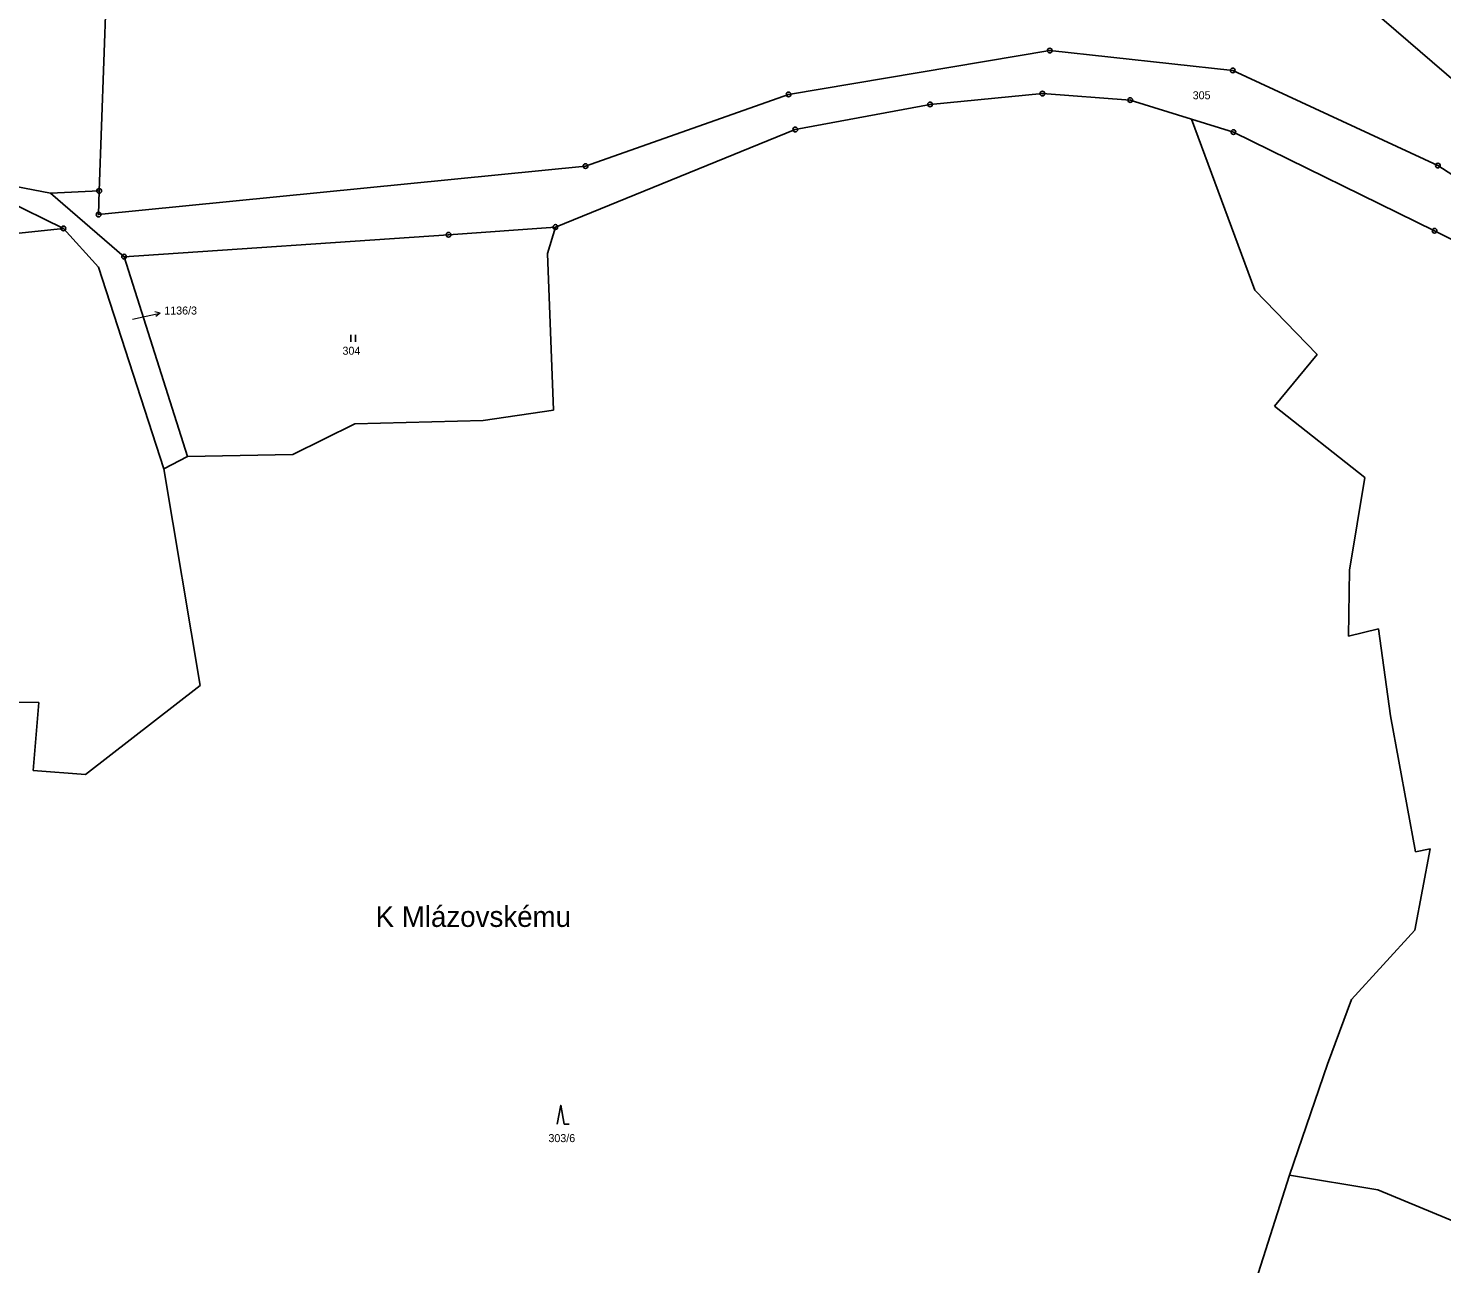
# Model space of a CAD drawing. Extents: x -765428 to -762163, y -1107632 to -1104975.
# Drawn here: x -763569.2 to -763268.9, y -1106861.1 to -1106598.6 of the extents above; entities that cross this region are included whole.
import ezdxf

# ---------------------------------------------------------------- set-up
doc = ezdxf.new("R2010")
doc.units = 0
doc.header["$LTSCALE"] = 0.68
for name, color, linetype, lineweight in [('1', 7, 'Continuous', 25), ('3', 7, 'Continuous', 25), ('7', 7, 'Continuous', 13), ('8', 7, 'Continuous', 25)]:
    doc.layers.add(name, color=color, linetype=linetype, lineweight=lineweight)
doc.layers.add('2', color=7, linetype='Continuous')

msp = doc.modelspace()

# ---------------------------------------------------------------- linework, layer by layer
at = {"layer": '1'}
for p, q in [((-763552.49, -1106587.5), (-763554.12, -1106633.15)), ((-763284.2, -1106594.34), (-763265.37, -1106610.51)), ((-763352.19, -1106603.34), (-763407.67, -1106612.64)), ((-763313.3, -1106607.56), (-763352.19, -1106603.34)), ((-763269.72, -1106627.78), (-763313.3, -1106607.56)), ((-763407.67, -1106612.64), (-763450.79, -1106627.87)), ((-763377.61, -1106614.76), (-763406.25, -1106620.1)), ((-763353.75, -1106612.47), (-763377.61, -1106614.76)), ((-763335.07, -1106613.84), (-763353.75, -1106612.47)), ((-763322.09, -1106617.87), (-763335.07, -1106613.84)), ((-763308.58, -1106654.21), (-763322.09, -1106617.87)), ((-763313.15, -1106620.65), (-763322.09, -1106617.87)), ((-763406.25, -1106620.1), (-763457.18, -1106640.82)), ((-763270.44, -1106641.61), (-763313.15, -1106620.65)), ((-763564.46, -1106633.61), (-763588.74, -1106629.05)), ((-763554.26, -1106638.18), (-763450.79, -1106627.87)), ((-763247.51, -1106642.16), (-763269.72, -1106627.78)), ((-763561.73, -1106641.13), (-763574.06, -1106635.01)), ((-763554.12, -1106633.15), (-763564.46, -1106633.61)), ((-763548.81, -1106647.12), (-763564.46, -1106633.61)), ((-763554.12, -1106633.15), (-763554.26, -1106638.18)), ((-763582.01, -1106643.26), (-763561.73, -1106641.13)), ((-763561.73, -1106641.13), (-763554.28, -1106649.38)), ((-763457.18, -1106640.82), (-763479.9, -1106642.48)), ((-763458.89, -1106646.44), (-763457.18, -1106640.82)), ((-763243.17, -1106655.54), (-763270.44, -1106641.61)), ((-763479.9, -1106642.48), (-763548.81, -1106647.12)), ((-763548.81, -1106647.12), (-763535.32, -1106689.59)), ((-763457.61, -1106679.72), (-763458.89, -1106646.44)), ((-763554.28, -1106649.38), (-763540.36, -1106692.2)), ((-763308.58, -1106654.21), (-763295.34, -1106667.93)), ((-763295.34, -1106667.93), (-763304.45, -1106678.85)), ((-763472.56, -1106681.93), (-763457.61, -1106679.72)), ((-763304.45, -1106678.85), (-763285.25, -1106694.03)), ((-763513, -1106689.13), (-763499.8, -1106682.66)), ((-763499.8, -1106682.66), (-763472.56, -1106681.93)), ((-763535.32, -1106689.59), (-763513, -1106689.13)), ((-763285.25, -1106694.03), (-763288.47, -1106713.74)), ((-763288.47, -1106713.74), (-763288.71, -1106727.75)), ((-763288.71, -1106727.75), (-763282.36, -1106726.2)), ((-763282.36, -1106726.2), (-763279.78, -1106744.65)), ((-763532.66, -1106738.23), (-763557, -1106757.15)), ((-763566.96, -1106741.84), (-763573.01, -1106741.77)), ((-763568.17, -1106756.29), (-763566.96, -1106741.84)), ((-763279.78, -1106744.65), (-763274.45, -1106773.56)), ((-763557, -1106757.15), (-763568.17, -1106756.29)), ((-763271.36, -1106772.92), (-763274.64, -1106790.23)), ((-763274.45, -1106773.56), (-763271.36, -1106772.92)), ((-763274.64, -1106790.23), (-763288.09, -1106804.94)), ((-763288.09, -1106804.94), (-763293.17, -1106818.66)), ((-763293.17, -1106818.66), (-763301.28, -1106842.27)), ((-763301.28, -1106842.27), (-763317.91, -1106894.73)), ((-763282.5, -1106845.36), (-763301.28, -1106842.27)), ((-763282.5, -1106845.36), (-763258.36, -1106855.43))]:
    msp.add_line(p, q, dxfattribs=at)
msp.add_lwpolyline([(-763535.32, -1106689.59), (-763540.36, -1106692.2), (-763532.66, -1106738.23)], dxfattribs=at)
at = {"layer": '3'}
for p, q in [((-763500.661, -1106665.2), (-763500.661, -1106663.7)), ((-763499.66, -1106665.2), (-763499.66, -1106663.7)), ((-763455.3, -1106831.42), (-763454.304, -1106831.42))]:
    msp.add_line(p, q, dxfattribs=at)
msp.add_lwpolyline([(-763455.3, -1106831.42), (-763456.05, -1106827.42), (-763456.8, -1106831.42)], dxfattribs=at)
at = {"layer": '7'}
msp.add_line((-763541.185, -1106659.136), (-763542.268, -1106658.854), dxfattribs=at)
msp.add_lwpolyline([(-763547.02, -1106660.39), (-763544.12, -1106659.76), (-763541.185, -1106659.136), (-763542.06, -1106659.834)], dxfattribs=at)
at = {"layer": '8'}
for centre, radius in [((-763352.19, -1106603.3399), 0.5), ((-763352.19, -1106603.3399), 0.0303), ((-763313.3, -1106607.5599), 0.5), ((-763313.3, -1106607.5599), 0.0303), ((-763353.75, -1106612.4699), 0.5), ((-763407.67, -1106612.6399), 0.5), ((-763407.67, -1106612.6399), 0.0303), ((-763377.61, -1106614.7599), 0.5), ((-763377.61, -1106614.7599), 0.0303), ((-763353.75, -1106612.4699), 0.0303), ((-763335.07, -1106613.8399), 0.5), ((-763335.07, -1106613.8399), 0.0303), ((-763406.25, -1106620.0999), 0.5), ((-763406.25, -1106620.0999), 0.0303), ((-763313.15, -1106620.6499), 0.5), ((-763313.15, -1106620.6499), 0.0303), ((-763450.79, -1106627.8699), 0.5), ((-763450.79, -1106627.8699), 0.0303), ((-763269.72, -1106627.7799), 0.5), ((-763269.72, -1106627.7799), 0.0303), ((-763554.12, -1106633.1499), 0.5), ((-763554.12, -1106633.1499), 0.0303), ((-763554.26, -1106638.1799), 0.5), ((-763554.26, -1106638.1799), 0.0303), ((-763561.73, -1106641.1299), 0.5), ((-763561.73, -1106641.1299), 0.0303), ((-763479.9, -1106642.4799), 0.5), ((-763457.18, -1106640.8199), 0.5), ((-763457.18, -1106640.8199), 0.0303), ((-763270.44, -1106641.6099), 0.5), ((-763270.44, -1106641.6099), 0.0303), ((-763479.9, -1106642.4799), 0.0303), ((-763548.81, -1106647.1199), 0.5), ((-763548.81, -1106647.1199), 0.0303)]:
    msp.add_circle(centre, radius, dxfattribs=at)

# ---------------------------------------------------------------- texts
at = {"layer": '2'}
for s, p in [('305', (-763321.81, -1106613.675)), ('1136/3', (-763540.29, -1106659.415)), ('304', (-763502.43, -1106667.955)), ('303/6', (-763458.68, -1106835.255))]:
    msp.add_text(s, height=1.7, dxfattribs=at).set_placement(p)
at = {"layer": '7'}
msp.add_text('K Mlázovskému', height=4.4, dxfattribs=at).set_placement((-763495.4, -1106789.53))

doc.saveas('drawing.dxf')
